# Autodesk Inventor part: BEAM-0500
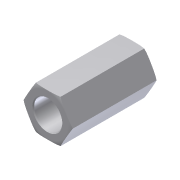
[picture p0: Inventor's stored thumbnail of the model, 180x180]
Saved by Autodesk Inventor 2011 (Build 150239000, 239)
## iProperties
Created: 2008-05
Part Number: BEAM-0500
Document SubType Name: Modeling
Density: 1 g/cm^3
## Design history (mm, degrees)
feature "Base1"
body "Solid1"
